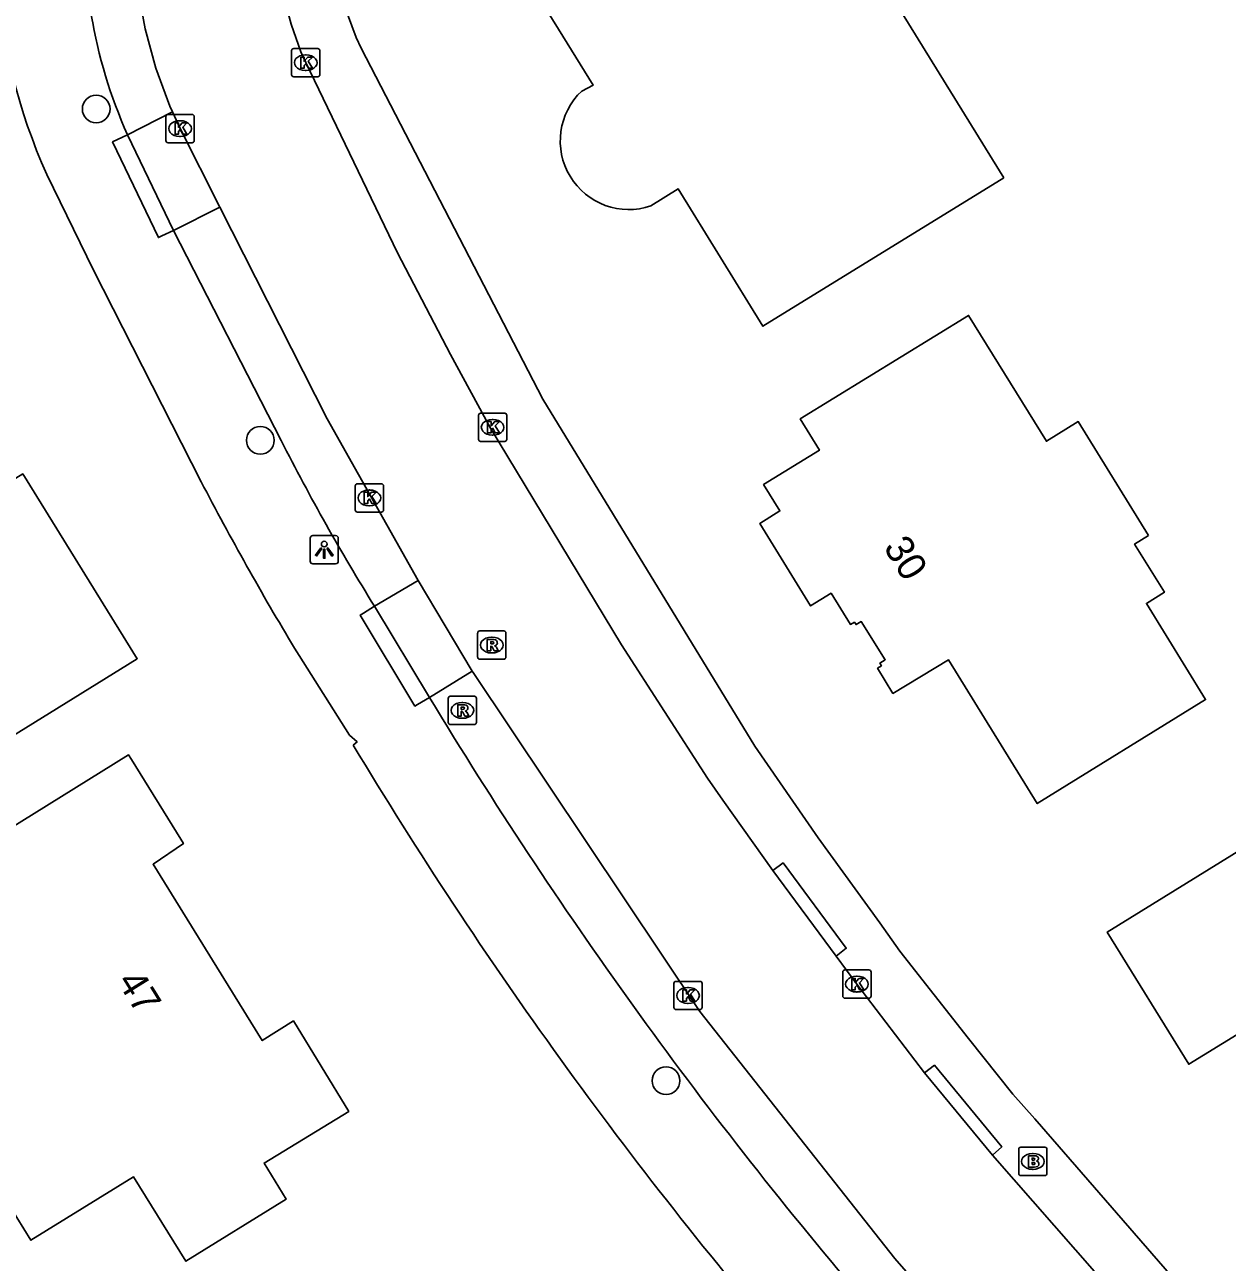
# Model space of a CAD drawing. Extents: x 158838 to 160074, y 386376 to 387776.
# Drawn here: x 159273.38 to 159315.93, y 386659.86 to 386703.65 of the extents above; entities that cross this region are included whole.
import ezdxf

# ---------------------------------------------------------------- set-up
doc = ezdxf.new("R2010")
doc.units = 0
for name, color, linetype in [('IMGEO_Boom', 7, 'Continuous'), ('IMGEO_Brandkraan', 7, 'Continuous'), ('IMGEO_Kolk', 7, 'Continuous'), ('IMGEO_Lichtpunt', 7, 'Continuous'), ('IMGEO_Pand', 7, 'Continuous'), ('IMGEO_Pand_nummerreeks', 7, 'Continuous'), ('IMGEO_Rijbaan_lokaal_gesloten', 7, 'Continuous'), ('IMGEO_Rioolput', 7, 'Continuous'), ('IMGEO_Voetpad_open', 7, 'Continuous')]:
    doc.layers.add(name, color=color, linetype=linetype)

msp = doc.modelspace()

# ---------------------------------------------------------------- linework, layer by layer
at = {"layer": 'IMGEO_Boom'}
for centre in [(159275.907, 386700.667), (159281.714, 386688.943), (159296.07, 386666.283)]:
    msp.add_circle(centre, 0.489, dxfattribs=at)
at = {"layer": 'IMGEO_Brandkraan'}
for p, q in [((159308.546, 386663.001), (159308.546, 386663.853)), ((159308.621, 386663.927), (159309.473, 386663.927)), ((159309.034, 386663.707), (159309.059, 386663.707)), ((159309.547, 386663.853), (159309.547, 386663.001)), ((159309.473, 386662.927), (159308.621, 386662.927)), ((159309.057, 386663.147), (159309.032, 386663.147))]:
    msp.add_line(p, q, dxfattribs=at)
for points in [[(159308.546, 386663.001), (159308.546, 386663.853)], [(159308.621, 386663.927), (159309.473, 386663.927)], [(159309.547, 386663.853), (159309.547, 386663.001)], [(159308.894, 386663.627), (159308.894, 386663.227), (159309.107, 386663.227)], [(159309.125, 386663.627), (159308.894, 386663.627)], [(159309.073, 386663.546), (159309.019, 386663.546), (159309.019, 386663.47)], [(159309.019, 386663.47), (159309.072, 386663.47)], [(159309.081, 386663.394), (159309.019, 386663.394), (159309.019, 386663.313)], [(159309.019, 386663.313), (159309.081, 386663.313)], [(159309.473, 386662.927), (159308.621, 386662.927)]]:
    msp.add_lwpolyline(points, dxfattribs=at)
for centre, radius, start, end in [((159308.623, 386663.851), 0.0765, 91.552, 178.448), ((159308.623, 386663.851), 0.0765, 91.552, 178.448), ((159309.471, 386663.851), 0.0765, 1.552, 88.448), ((159309.471, 386663.851), 0.0765, 1.552, 88.448), ((159309.074, 386663.508), 0.0379, 267.8285, 90.9355), ((159309.082, 386663.353), 0.0404, 269.8759, 90.5077), ((159309.129, 386663.482), 0.145, 59.4692, 91.5367), ((159309.154, 386663.529), 0.0922, 285.5137, 58.1501), ((159309.159, 386663.337), 0.105, 301.3115, 78.989), ((159308.623, 386663.003), 0.0765, 181.552, 268.448), ((159308.623, 386663.003), 0.0765, 181.552, 268.448), ((159309.113, 386663.478), 0.251, 268.6676, 293.5347), ((159309.471, 386663.003), 0.0765, 271.552, 358.448), ((159309.471, 386663.003), 0.0765, 271.552, 358.448)]:
    msp.add_arc(centre, radius, start, end, dxfattribs=at)
for centre, major_axis, ratio, start_param, end_param in [((159309.033, 386663.427), (-0.387, 0.002), 0.722429, 4.712389, 7.853982), ((159309.058, 386663.427), (-0.39, 0.002), 0.717154, 1.570796, 4.712389)]:
    msp.add_ellipse(centre, major_axis=major_axis, ratio=ratio, start_param=start_param, end_param=end_param, dxfattribs=at)
at = {"layer": 'IMGEO_Kolk'}
for p, q in [((159282.821, 386701.88), (159282.821, 386702.732)), ((159282.896, 386702.806), (159283.748, 386702.806)), ((159283.822, 386702.732), (159283.822, 386701.88)), ((159283.309, 386702.586), (159283.334, 386702.586)), ((159283.748, 386701.806), (159282.896, 386701.806)), ((159283.332, 386702.026), (159283.307, 386702.026)), ((159278.45, 386700.473), (159279.302, 386700.473)), ((159278.375, 386699.547), (159278.375, 386700.399)), ((159278.863, 386700.253), (159278.888, 386700.253)), ((159279.376, 386700.399), (159279.376, 386699.547)), ((159278.886, 386699.693), (159278.861, 386699.693)), ((159279.302, 386699.473), (159278.45, 386699.473)), ((159289.434, 386688.977), (159289.434, 386689.829)), ((159289.509, 386689.903), (159290.361, 386689.903)), ((159289.922, 386689.683), (159289.947, 386689.683)), ((159290.435, 386689.829), (159290.435, 386688.977)), ((159289.945, 386689.123), (159289.92, 386689.123)), ((159290.361, 386688.903), (159289.509, 386688.903)), ((159285.147, 386687.405), (159285.999, 386687.405)), ((159285.072, 386686.479), (159285.072, 386687.331)), ((159285.56, 386687.185), (159285.585, 386687.185)), ((159286.073, 386687.331), (159286.073, 386686.479)), ((159285.583, 386686.625), (159285.558, 386686.625)), ((159285.999, 386686.405), (159285.147, 386686.405)), ((159302.322, 386669.276), (159302.322, 386670.128)), ((159302.397, 386670.202), (159303.249, 386670.202)), ((159302.81, 386669.982), (159302.835, 386669.982)), ((159303.323, 386670.128), (159303.323, 386669.276)), ((159296.346, 386668.873), (159296.346, 386669.725)), ((159296.421, 386669.799), (159297.273, 386669.799)), ((159296.834, 386669.579), (159296.859, 386669.579)), ((159297.347, 386669.725), (159297.347, 386668.873)), ((159302.833, 386669.422), (159302.808, 386669.422)), ((159296.857, 386669.019), (159296.832, 386669.019)), ((159303.249, 386669.202), (159302.397, 386669.202)), ((159297.273, 386668.799), (159296.421, 386668.799))]:
    msp.add_line(p, q, dxfattribs=at)
for points in [[(159282.821, 386701.88), (159282.821, 386702.732)], [(159282.896, 386702.806), (159283.748, 386702.806)], [(159283.822, 386702.732), (159283.822, 386701.88)], [(159283.142, 386702.506), (159283.265, 386702.506), (159283.265, 386702.355), (159283.395, 386702.506), (159283.559, 386702.506), (159283.413, 386702.355), (159283.566, 386702.106), (159283.414, 386702.106), (159283.329, 386702.27), (159283.265, 386702.203), (159283.265, 386702.106), (159283.142, 386702.106), (159283.142, 386702.506)], [(159283.748, 386701.806), (159282.896, 386701.806)], [(159278.45, 386700.473), (159279.302, 386700.473)], [(159278.375, 386699.547), (159278.375, 386700.399)], [(159278.696, 386700.173), (159278.819, 386700.173), (159278.819, 386700.022), (159278.949, 386700.173), (159279.113, 386700.173), (159278.967, 386700.022), (159279.12, 386699.773), (159278.968, 386699.773), (159278.883, 386699.937), (159278.819, 386699.87), (159278.819, 386699.773), (159278.696, 386699.773), (159278.696, 386700.173)], [(159279.376, 386700.399), (159279.376, 386699.547)], [(159279.302, 386699.473), (159278.45, 386699.473)], [(159289.434, 386688.977), (159289.434, 386689.829)], [(159289.509, 386689.903), (159290.361, 386689.903)], [(159289.755, 386689.603), (159289.878, 386689.603), (159289.878, 386689.452), (159290.008, 386689.603), (159290.172, 386689.603), (159290.026, 386689.452), (159290.179, 386689.203), (159290.027, 386689.203), (159289.942, 386689.367), (159289.878, 386689.3), (159289.878, 386689.203), (159289.755, 386689.203), (159289.755, 386689.603)], [(159290.435, 386689.829), (159290.435, 386688.977)], [(159290.361, 386688.903), (159289.509, 386688.903)], [(159285.147, 386687.405), (159285.999, 386687.405)], [(159285.072, 386686.479), (159285.072, 386687.331)], [(159285.393, 386687.105), (159285.516, 386687.105), (159285.516, 386686.954), (159285.646, 386687.105), (159285.81, 386687.105), (159285.664, 386686.954), (159285.817, 386686.705), (159285.665, 386686.705), (159285.58, 386686.869), (159285.516, 386686.802), (159285.516, 386686.705), (159285.393, 386686.705), (159285.393, 386687.105)], [(159286.073, 386687.331), (159286.073, 386686.479)], [(159285.999, 386686.405), (159285.147, 386686.405)], [(159302.322, 386669.276), (159302.322, 386670.128)], [(159302.397, 386670.202), (159303.249, 386670.202)], [(159302.643, 386669.902), (159302.766, 386669.902), (159302.766, 386669.751), (159302.896, 386669.902), (159303.06, 386669.902), (159302.914, 386669.751), (159303.067, 386669.502), (159302.915, 386669.502), (159302.83, 386669.666), (159302.766, 386669.599), (159302.766, 386669.502), (159302.643, 386669.502), (159302.643, 386669.902)], [(159303.323, 386670.128), (159303.323, 386669.276)], [(159296.346, 386668.873), (159296.346, 386669.725)], [(159296.421, 386669.799), (159297.273, 386669.799)], [(159296.667, 386669.499), (159296.79, 386669.499), (159296.79, 386669.348), (159296.92, 386669.499), (159297.084, 386669.499), (159296.938, 386669.348), (159297.091, 386669.099), (159296.939, 386669.099), (159296.854, 386669.263), (159296.79, 386669.196), (159296.79, 386669.099), (159296.667, 386669.099), (159296.667, 386669.499)], [(159297.347, 386669.725), (159297.347, 386668.873)], [(159303.249, 386669.202), (159302.397, 386669.202)], [(159297.273, 386668.799), (159296.421, 386668.799)]]:
    msp.add_lwpolyline(points, dxfattribs=at)
for centre, start, end in [((159282.898, 386702.73), 91.552, 178.448), ((159282.898, 386702.73), 91.552, 178.448), ((159283.746, 386702.73), 1.552, 88.448), ((159283.746, 386702.73), 1.552, 88.448), ((159282.898, 386701.882), 181.552, 268.448), ((159282.898, 386701.882), 181.552, 268.448), ((159283.746, 386701.882), 271.552, 358.448), ((159283.746, 386701.882), 271.552, 358.448), ((159278.452, 386700.397), 91.552, 178.448), ((159278.452, 386700.397), 91.552, 178.448), ((159279.3, 386700.397), 1.552, 88.448), ((159279.3, 386700.397), 1.552, 88.448), ((159278.452, 386699.549), 181.552, 268.448), ((159278.452, 386699.549), 181.552, 268.448), ((159279.3, 386699.549), 271.552, 358.448), ((159279.3, 386699.549), 271.552, 358.448), ((159289.511, 386689.827), 91.552, 178.448), ((159289.511, 386689.827), 91.552, 178.448), ((159290.359, 386689.827), 1.552, 88.448), ((159290.359, 386689.827), 1.552, 88.448), ((159289.511, 386688.979), 181.552, 268.448), ((159289.511, 386688.979), 181.552, 268.448), ((159290.359, 386688.979), 271.552, 358.448), ((159290.359, 386688.979), 271.552, 358.448), ((159285.149, 386687.329), 91.552, 178.448), ((159285.149, 386687.329), 91.552, 178.448), ((159285.997, 386687.329), 1.552, 88.448), ((159285.997, 386687.329), 1.552, 88.448), ((159285.149, 386686.481), 181.552, 268.448), ((159285.149, 386686.481), 181.552, 268.448), ((159285.997, 386686.481), 271.552, 358.448), ((159285.997, 386686.481), 271.552, 358.448), ((159302.399, 386670.126), 91.552, 178.448), ((159302.399, 386670.126), 91.552, 178.448), ((159303.247, 386670.126), 1.552, 88.448), ((159303.247, 386670.126), 1.552, 88.448), ((159296.423, 386669.723), 91.552, 178.448), ((159296.423, 386669.723), 91.552, 178.448), ((159297.271, 386669.723), 1.552, 88.448), ((159297.271, 386669.723), 1.552, 88.448), ((159302.399, 386669.278), 181.552, 268.448), ((159302.399, 386669.278), 181.552, 268.448), ((159303.247, 386669.278), 271.552, 358.448), ((159303.247, 386669.278), 271.552, 358.448), ((159296.423, 386668.875), 181.552, 268.448), ((159296.423, 386668.875), 181.552, 268.448), ((159297.271, 386668.875), 271.552, 358.448), ((159297.271, 386668.875), 271.552, 358.448)]:
    msp.add_arc(centre, 0.0765, start, end, dxfattribs=at)
for centre, major_axis, ratio, start_param, end_param in [((159283.308, 386702.306), (-0.387, 0.002), 0.722429, 4.712389, 7.853982), ((159283.333, 386702.306), (-0.39, 0.002), 0.717154, 1.570796, 4.712389), ((159278.862, 386699.973), (-0.387, 0.002), 0.722429, 4.712389, 7.853982), ((159278.887, 386699.973), (-0.39, 0.002), 0.717154, 1.570796, 4.712389), ((159289.921, 386689.403), (-0.387, 0.002), 0.722429, 4.712389, 7.853982), ((159289.946, 386689.403), (-0.39, 0.002), 0.717154, 1.570796, 4.712389), ((159285.559, 386686.905), (-0.387, 0.002), 0.722429, 4.712389, 7.853982), ((159285.584, 386686.905), (-0.39, 0.002), 0.717154, 1.570796, 4.712389), ((159302.809, 386669.702), (-0.387, 0.002), 0.722429, 4.712389, 7.853982), ((159302.834, 386669.702), (-0.39, 0.002), 0.717154, 1.570796, 4.712389), ((159296.833, 386669.299), (-0.387, 0.002), 0.722429, 4.712389, 7.853982), ((159296.858, 386669.299), (-0.39, 0.002), 0.717154, 1.570796, 4.712389)]:
    msp.add_ellipse(centre, major_axis=major_axis, ratio=ratio, start_param=start_param, end_param=end_param, dxfattribs=at)
at = {"layer": 'IMGEO_Lichtpunt'}
for p, q in [((159283.477, 386685.475), (159283.477, 386684.668)), ((159283.477, 386685.475), (159283.477, 386684.668)), ((159284.379, 386685.57), (159283.571, 386685.57)), ((159284.379, 386685.57), (159283.571, 386685.57)), ((159284.473, 386684.668), (159284.473, 386685.475)), ((159284.473, 386684.668), (159284.473, 386685.475)), ((159283.571, 386684.574), (159284.379, 386684.574)), ((159283.571, 386684.574), (159284.379, 386684.574))]:
    msp.add_line(p, q, dxfattribs=at)
for points in [[(159283.851, 386685.139), (159283.89, 386685.111), (159283.702, 386684.849), (159283.664, 386684.876), (159283.851, 386685.139)], [(159283.953, 386685.091), (159284, 386685.091), (159284, 386684.769), (159283.953, 386684.769), (159283.953, 386685.091)], [(159284.063, 386685.111), (159284.101, 386685.138), (159284.288, 386684.876), (159284.249, 386684.848), (159284.063, 386685.111)]]:
    msp.add_lwpolyline(points, dxfattribs=at)
msp.add_circle((159283.976, 386685.273), 0.0994, dxfattribs=at)
for centre, start, end in [((159283.571, 386685.475), 90, 180), ((159283.571, 386685.475), 90, 180), ((159284.379, 386685.475), 0, 90), ((159284.379, 386685.475), 0, 90), ((159283.571, 386684.668), 180, 270), ((159283.571, 386684.668), 180, 270), ((159284.379, 386684.668), 270, 0), ((159284.379, 386684.668), 270, 360)]:
    msp.add_arc(centre, 0.0946, start, end, dxfattribs=at)
at = {"layer": 'IMGEO_Pand'}
for points in [[(159293.089, 386701.303), (159293.486, 386701.509), (159290.822, 386705.829), (159291.826, 386706.448), (159290.847, 386708.063), (159289.847, 386707.437), (159289.448, 386708.074), (159290.379, 386708.645), (159289.858, 386709.5), (159293.768, 386711.923), (159292.114, 386714.607), (159294.178, 386719.374), (159294.985, 386719.024), (159298.628, 386727.367), (159304.218, 386722.599), (159302.078, 386717.823), (159304.926, 386713.21), (159300.468, 386710.457), (159308.016, 386698.233)], [(159308.016, 386698.233), (159299.496, 386692.978), (159296.496, 386697.842), (159295.536, 386697.238)], [(159267.545, 386675.138), (159277.357, 386681.213), (159273.306, 386687.757), (159272.124, 386687.031), (159270.766, 386689.22), (159269.86, 386688.668), (159266.592, 386693.832), (159266.966, 386694.064), (159266.455, 386694.89), (159262.23, 386692.216), (159251.173, 386685.55), (159257.115, 386675.888), (159261.048, 386678.307), (159260.869, 386678.598), (159264.169, 386680.627), (159267.545, 386675.138)], [(159313.14, 386685.575), (159312.648, 386685.272), (159313.7, 386683.565), (159313.063, 386683.173), (159315.161, 386679.769), (159309.206, 386676.09), (159306.061, 386681.18), (159304.096, 386679.985), (159303.553, 386680.877), (159303.687, 386680.965), (159303.634, 386681.063), (159303.823, 386681.177), (159302.979, 386682.529), (159302.794, 386682.421), (159302.736, 386682.507), (159302.592, 386682.427), (159301.908, 386683.533), (159301.186, 386683.085), (159299.382, 386685.995), (159300.101, 386686.445), (159299.523, 386687.379), (159301.497, 386688.594), (159300.818, 386689.699), (159306.773, 386693.364), (159309.526, 386688.911), (159310.655, 386689.607), (159313.14, 386685.575)], [(159329.817, 386675.621), (159327.278, 386674.054), (159330.286, 386669.169), (159328.114, 386667.832), (159328.533, 386667.15), (159326.085, 386665.645), (159325.631, 386666.295), (159323.476, 386664.962), (159321.477, 386668.208), (159321.188, 386668.685), (159320.295, 386668.147), (159319.082, 386668.437), (159318.53, 386669.315), (159317.99, 386668.971), (159314.565, 386666.863), (159311.678, 386671.543), (159317.295, 386675.008), (159316.98, 386675.518), (159319.157, 386676.861), (159321.606, 386678.371), (159323.783, 386679.714), (159324.005, 386679.354), (159326.547, 386680.922), (159329.817, 386675.621)], [(159278.898, 386674.829), (159277.151, 386677.648), (159277.051, 386677.81), (159269.928, 386673.396), (159271.688, 386670.556), (159268.627, 386668.659), (159273.597, 386660.638), (159277.226, 386662.887), (159279.081, 386659.894), (159282.633, 386662.095), (159281.845, 386663.367), (159284.842, 386665.194), (159282.888, 386668.398), (159281.782, 386667.704), (159277.918, 386673.944), (159278.994, 386674.674), (159278.898, 386674.829)]]:
    msp.add_lwpolyline(points, dxfattribs=at)
msp.add_arc((159294.754, 386699.536), 2.428, 133.2959, 288.7973, dxfattribs=at)
at = {"layer": 'IMGEO_Rijbaan_lokaal_gesloten'}
for points in [[(159283.52, 386712.398), (159283.261, 386711.773), (159282.886, 386710.806), (159282.6, 386709.81), (159282.403, 386708.793), (159282.298, 386707.761), (159282.286, 386706.725), (159282.366, 386705.691), (159282.539, 386704.669), (159282.802, 386703.667), (159283.153, 386702.691), (159283.32, 386702.306), (159286.568, 386695.579), (159288.449, 386691.977), (159289.859, 386689.376), (159294.493, 386681.712), (159297.54, 386676.987), (159298.08, 386676.211), (159299.845, 386673.724)], [(159278.609, 386700.563), (159278.516, 386700.767), (159278.015, 386702.116), (159277.636, 386703.504), (159277.382, 386704.921), (159277.256, 386706.354), (159277.258, 386707.793), (159277.389, 386709.226), (159277.648, 386710.642)], [(159278.609, 386700.563), (159278.878, 386699.974), (159280.284, 386697.196)], [(159280.284, 386697.196), (159284.075, 386689.709), (159287.3, 386683.98)], [(159287.3, 386683.98), (159289.215, 386680.779)], [(159311.528, 386651.956), (159308.966, 386654.479), (159304.162, 386659.994), (159297.263, 386668.731), (159289.242, 386680.733), (159289.215, 386680.779)], [(159302.089, 386670.692), (159299.845, 386673.724)], [(159302.089, 386670.692), (159302.822, 386669.701), (159305.212, 386666.564)], [(159307.616, 386663.65), (159305.212, 386666.564)], [(159307.616, 386663.65), (159312.743, 386657.805), (159314.969, 386655.443)]]:
    msp.add_lwpolyline(points, dxfattribs=at)
at = {"layer": 'IMGEO_Rioolput'}
for p, q in [((159289.404, 386681.272), (159289.404, 386682.124)), ((159289.479, 386682.198), (159290.331, 386682.198)), ((159290.405, 386682.124), (159290.405, 386681.272)), ((159289.892, 386681.978), (159289.917, 386681.978)), ((159289.915, 386681.418), (159289.89, 386681.418)), ((159290.331, 386681.198), (159289.479, 386681.198)), ((159288.362, 386678.96), (159288.362, 386679.812)), ((159288.437, 386679.886), (159289.289, 386679.886)), ((159288.85, 386679.666), (159288.875, 386679.666)), ((159289.363, 386679.812), (159289.363, 386678.96)), ((159288.873, 386679.106), (159288.848, 386679.106)), ((159289.289, 386678.886), (159288.437, 386678.886))]:
    msp.add_line(p, q, dxfattribs=at)
for points in [[(159289.404, 386681.272), (159289.404, 386682.124)], [(159289.479, 386682.198), (159290.331, 386682.198)], [(159290.405, 386682.124), (159290.405, 386681.272)], [(159289.993, 386681.896), (159289.741, 386681.898), (159289.741, 386681.498)], [(159289.741, 386681.498), (159289.865, 386681.498), (159289.865, 386681.66), (159289.876, 386681.66)], [(159289.919, 386681.817), (159289.865, 386681.817), (159289.865, 386681.736)], [(159289.865, 386681.736), (159289.917, 386681.736)], [(159289.923, 386681.631), (159289.994, 386681.498), (159290.134, 386681.498), (159290.069, 386681.624)], [(159290.331, 386681.198), (159289.479, 386681.198)], [(159288.362, 386678.96), (159288.362, 386679.812)], [(159288.437, 386679.886), (159289.289, 386679.886)], [(159288.951, 386679.584), (159288.699, 386679.586), (159288.699, 386679.186)], [(159288.877, 386679.505), (159288.823, 386679.505), (159288.823, 386679.424)], [(159289.363, 386679.812), (159289.363, 386678.96)], [(159288.699, 386679.186), (159288.823, 386679.186), (159288.823, 386679.348), (159288.834, 386679.348)], [(159288.823, 386679.424), (159288.875, 386679.424)], [(159288.881, 386679.319), (159288.952, 386679.186), (159289.092, 386679.186), (159289.027, 386679.312)], [(159289.289, 386678.886), (159288.437, 386678.886)]]:
    msp.add_lwpolyline(points, dxfattribs=at)
for centre, radius, start, end in [((159289.481, 386682.122), 0.0765, 91.552, 178.448), ((159289.481, 386682.122), 0.0765, 91.552, 178.448), ((159290.329, 386682.122), 0.0765, 1.552, 88.448), ((159290.329, 386682.122), 0.0765, 1.552, 88.448), ((159289.875, 386681.607), 0.0533, 26.0293, 88.6989), ((159289.901, 386681.925), 0.19, 274.7715, 282.9687), ((159289.925, 386681.721), 0.0964, 77.0061, 93.1865), ((159289.939, 386681.778), 0.0378, 276.6634, 79.6772), ((159289.992, 386681.786), 0.109, 350.3612, 89.416), ((159289.99, 386681.786), 0.112, 277.5842, 350.9817), ((159289.974, 386681.571), 0.108, 29.5134, 73.7905), ((159289.481, 386681.274), 0.0765, 181.552, 268.448), ((159289.481, 386681.274), 0.0765, 181.552, 268.448), ((159290.329, 386681.274), 0.0765, 271.552, 358.448), ((159290.329, 386681.274), 0.0765, 271.552, 358.448), ((159288.439, 386679.81), 0.0765, 91.552, 178.448), ((159288.439, 386679.81), 0.0765, 91.552, 178.448), ((159288.883, 386679.409), 0.0964, 77.0061, 93.1865), ((159288.897, 386679.466), 0.0378, 276.6634, 79.6772), ((159288.95, 386679.474), 0.109, 350.3612, 89.416), ((159288.948, 386679.474), 0.112, 277.5842, 350.9817), ((159289.287, 386679.81), 0.0765, 1.552, 88.448), ((159289.287, 386679.81), 0.0765, 1.552, 88.448), ((159288.833, 386679.295), 0.0533, 26.0293, 88.6989), ((159288.859, 386679.613), 0.19, 274.7715, 282.9687), ((159288.932, 386679.259), 0.108, 29.5134, 73.7905), ((159288.439, 386678.962), 0.0765, 181.552, 268.448), ((159288.439, 386678.962), 0.0765, 181.552, 268.448), ((159289.287, 386678.962), 0.0765, 271.552, 358.448), ((159289.287, 386678.962), 0.0765, 271.552, 358.448)]:
    msp.add_arc(centre, radius, start, end, dxfattribs=at)
for centre, major_axis, ratio, start_param, end_param in [((159289.891, 386681.698), (-0.387, 0.002), 0.722429, 4.712389, 7.853982), ((159289.916, 386681.698), (-0.39, 0.002), 0.717154, 1.570796, 4.712389), ((159288.849, 386679.386), (-0.387, 0.002), 0.722429, 4.712389, 7.853982), ((159288.874, 386679.386), (-0.39, 0.002), 0.717154, 1.570796, 4.712389)]:
    msp.add_ellipse(centre, major_axis=major_axis, ratio=ratio, start_param=start_param, end_param=end_param, dxfattribs=at)
at = {"layer": 'IMGEO_Voetpad_open'}
for points in [[(159314.122, 386659.18), (159309.121, 386664.939), (159308.337, 386665.804), (159306.768, 386667.782), (159304.346, 386670.869), (159303.638, 386671.874), (159301.454, 386674.875), (159299.208, 386678.123), (159291.715, 386690.4), (159285.288, 386702.815), (159285.109, 386703.2), (159284.793, 386704.019), (159284.551, 386704.864), (159284.385, 386705.726), (159284.297, 386706.6), (159284.288, 386707.479), (159284.357, 386708.355), (159284.504, 386709.221), (159284.728, 386710.07), (159285.027, 386710.896), (159285.398, 386711.692)], [(159277.014, 386699.755), (159278.609, 386700.563)], [(159278.638, 386696.363), (159278.226, 386696.173), (159278.109, 386696.119), (159276.489, 386699.502), (159277.014, 386699.755)], [(159277.014, 386699.755), (159278.638, 386696.363)], [(159274.157, 386698.347), (159275.817, 386694.968), (159279.623, 386687.477)], [(159278.638, 386696.363), (159280.284, 386697.196)], [(159282.453, 386688.933), (159278.638, 386696.363)], [(159287.3, 386683.98), (159285.752, 386683.075)], [(159287.699, 386679.848), (159287.28, 386679.597), (159287.182, 386679.538), (159285.252, 386682.759), (159285.368, 386682.832), (159285.752, 386683.075)], [(159285.752, 386683.075), (159287.699, 386679.848)], [(159282.928, 386681.585), (159283.089, 386681.331), (159284.873, 386678.511), (159285.137, 386678.27), (159284.999, 386678.16)], [(159289.215, 386680.779), (159287.699, 386679.848)], [(159299.845, 386673.724), (159300.213, 386673.992), (159302.445, 386670.968), (159302.089, 386670.692)], [(159305.212, 386666.564), (159305.567, 386666.828), (159307.949, 386663.943), (159307.616, 386663.65)]]:
    msp.add_lwpolyline(points, dxfattribs=at)
for centre, radius, start, end in [((159293.909, 386707.119), 21.612, 165.0855, 203.9454), ((159293.051, 386706.904), 17.559, 175.0652, 204.0246), ((159352.797, 386724.69), 78.91, 206.94502, 211.82806), ((159377.095, 386738.279), 109.917, 207.52836, 211.0504), ((159427.547, 386764.38), 163.411, 211.15101, 220.30929), ((159421.392, 386760.217), 159.174, 211.03223, 220.61805)]:
    msp.add_arc(centre, radius, start, end, dxfattribs=at)

# ---------------------------------------------------------------- texts
at = {"layer": 'IMGEO_Pand_nummerreeks'}
for s, rotation, p in [('30', 301.7885, (159303.742, 386685.157)), ('47', 301.7671, (159276.626, 386669.8))]:
    msp.add_text(s, height=1, rotation=rotation, dxfattribs=at).set_placement(p)

doc.saveas('drawing.dxf')
